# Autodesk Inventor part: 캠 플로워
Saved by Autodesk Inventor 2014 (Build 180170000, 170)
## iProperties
Created: 2025-09
Part Number: 캠 플로워
Material: 일반
Document SubType Name: Modeling
Designer: dg
Density: 1 g/cm^3
Appearance: 기본값
Author: dg
Author: jhkim
Organization: THK
Description: Cam Follower with a Hexagon Socket Model CF-A-
Creation Date: 2025-09-02
Sending System: Autodesk Inventor 2026
Preprocessor: ST-DEVELOPER v20.1
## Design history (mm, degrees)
node "캠 플로워1"
body "Solid1"
node "기준1"
